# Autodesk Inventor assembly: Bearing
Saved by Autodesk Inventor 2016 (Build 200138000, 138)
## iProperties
Created: 2015-08
Part Number: Bearing
Document SubType Name: Assembly
Designer: Ugljesa
ClientObjectVersion: 1
Author: Ugljesa
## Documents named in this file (2)
- C:\Users\Ugljesa\Desktop\Turbokompr\Assembly1\Design Accelerator\Bearing3.iam
- C:\Users\Ugljesa\Documents\Inventor\Content Center Files\R2016\en-US\BS 292 (V)\BS 292_ Part 1 - N 1005 - 25 x 47 x 12.ipt
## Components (1 placed, 1 different names)
1. BS 292: Part 1 (V) (Metric) N 1005 - 25 x 47 x 12:1
